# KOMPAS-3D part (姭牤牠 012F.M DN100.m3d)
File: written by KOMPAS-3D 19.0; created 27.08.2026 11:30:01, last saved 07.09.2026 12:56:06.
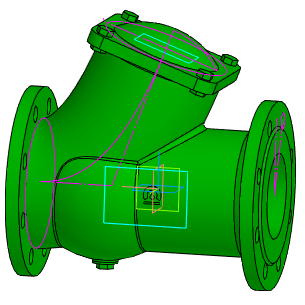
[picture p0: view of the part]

Document properties: Автор: Энергия; Полное имя файла: Z:\3.Личные\kachalov\001_3d для проектировщиков\х.х Тип 012F\012F.M\Клапан 012F.M DN100.m3d

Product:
- Part/product: (unnamed)  | designation Клапан 012F.M DN100
    Масса: 46.9835

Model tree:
1. Эскиз:1
2. Элемент вращения:1
     Угол 1 = 360
3. Эскиз:2  (with: Элемент вращения:1)
4. Перпендикулярная плоскость:1
5. Эскиз:3
6. Эскиз:12  (with: Элемент вращения:1)
7. Элемент по сечениям:1
8. Эскиз:7
9. Элемент выдавливания:2
     Расстояние 2 = 15
10. Эскиз:9  (with: Элемент выдавливания:2)
11. Элемент вращения:2
     Угол 1 = 360
12. Эскиз:10  (with: Элемент вращения:1)
13. Элемент выдавливания:3  (with: Элемент вращения:1)
     Расстояние 2 = 16
14. Массив по концентрической сетке:1  (with: Элемент выдавливания:3, Эскиз:10, Элемент вращения:1)  (8 pattern instances)
     Шаг 2 = 360
15. Эскиз:11  (with: Элемент вращения:1)
16. Элемент выдавливания:4  (with: Элемент вращения:1)
     Расстояние 2 = 16
17. Массив по концентрической сетке:2  (with: Элемент выдавливания:4, Эскиз:11, Элемент вращения:1)  (8 pattern instances)
     Шаг 2 = 360
18. Скругление:6  (with: Элемент выдавливания:2)
     Радиус = 3
19. Эскиз:13  (with: Элемент выдавливания:2)
20. Элемент выдавливания:5  (with: Элемент выдавливания:2)
     Расстояние 1 = 7; Смещение 2 = 5.5
21. Массив по концентрической сетке:3  (with: Элемент выдавливания:5, Эскиз:9, Эскиз:13, Элемент вращения:2)  (4 pattern instances)
     Шаг 2 = 360
22. Касательная плоскость:1  (with: Элемент вращения:1)
     Угол = 90
23. Смещенная плоскость:1
     Расстояние = 1
24. Эскиз:14
25. Элемент выдавливания:6  (with: Элемент вращения:1)
     Расстояние 1 = -1.00029; Расстояние 2 = 1
26. Эскиз:15  (with: Элемент вращения:1)
27. Элемент вращения:3  (with: Элемент вращения:1)
     Угол 1 = 360
28. Скругление:10  (with: Элемент вращения:3, Элемент по сечениям:1)
     Радиус = 5
29. Эскиз:16
30. Элемент выдавливания:7
     Расстояние 1 = 90
31. Эскиз:17  (with: Элемент выдавливания:7)
32. Элемент выдавливания:8
     Расстояние 1 = 6.5
33. Эскиз:18  (with: Элемент вращения:1)
34. Элемент выдавливания:9
     Расстояние 2 = 300
35. Скругление:11  (with: Элемент выдавливания:2)
     Радиус = 20
36. Скругление:12  (with: Элемент выдавливания:7)
     Радиус = 3
37. Эскиз:19  (with: Скругление:11, Элемент выдавливания:5)
38. Эскиз:20  (with: Скругление:11)

Expressions: Dn/2; D/2; D2/2; D2/2-5; 360/(2*n); 360/(n*2); D2-6; D2-5; 160/2
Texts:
  Клапан 012F.M DN100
